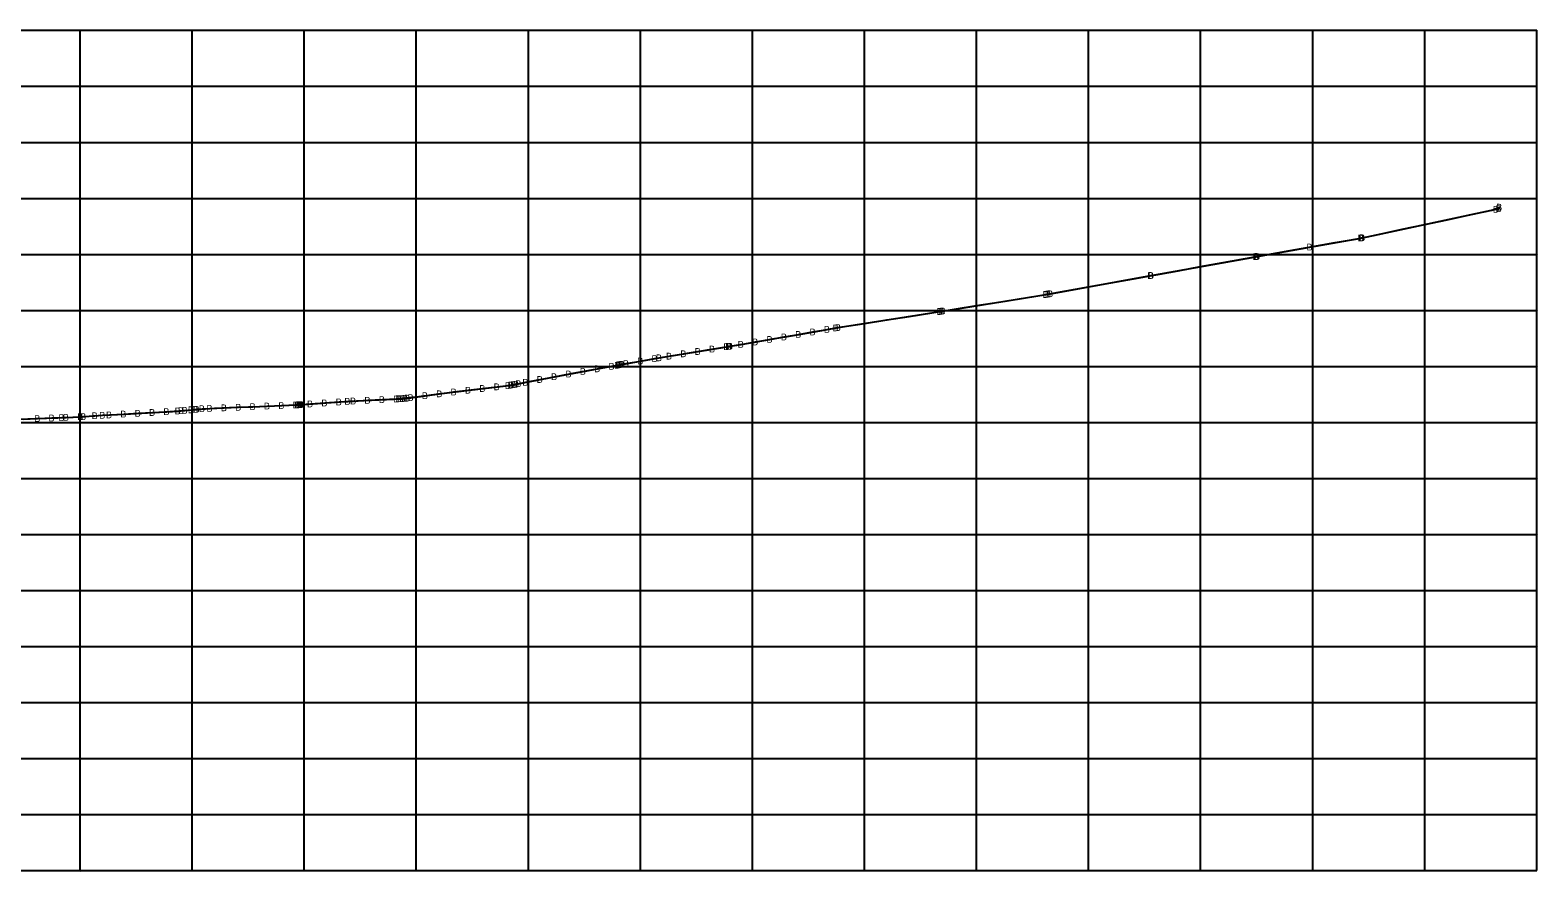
# Model space of a CAD drawing. Extents: x 76292 to 78417, y 50412 to 52585.
# Drawn here: x 77533 to 78206, y 50412 to 50787 of the extents above; entities that cross this region are included whole.
import ezdxf

# ---------------------------------------------------------------- set-up
doc = ezdxf.new("R2010")
doc.units = 0
for name, color, linetype in [('1', 7, 'Continuous'), ('2', 7, 'Continuous'), ('38', 7, 'Continuous'), ('5', 7, 'Continuous'), ('63', 7, 'Continuous')]:
    doc.layers.add(name, color=color, linetype=linetype)

msp = doc.modelspace()

# ---------------------------------------------------------------- linework, layer by layer
at = {"layer": '1'}
for p, q in [((76305.34, 50412.34), (78205.34, 50412.34)), ((77555.34, 50412.34), (77555.34, 50412.34)), ((77605.34, 50412.34), (77605.34, 50412.34)), ((77655.34, 50412.34), (77655.34, 50412.34)), ((77705.34, 50412.34), (77705.34, 50412.34)), ((77755.34, 50412.34), (77755.34, 50412.34)), ((77805.34, 50412.34), (77805.34, 50412.34)), ((77855.34, 50412.34), (77855.34, 50412.34)), ((77905.34, 50412.34), (77905.34, 50412.34)), ((77955.34, 50412.34), (77955.34, 50412.34)), ((78005.34, 50412.34), (78005.34, 50412.34)), ((78055.34, 50412.34), (78055.34, 50412.34)), ((78105.34, 50412.34), (78105.34, 50412.34)), ((78155.34, 50412.34), (78155.34, 50412.34)), ((78205.34, 50412.34), (78205.34, 50412.34))]:
    msp.add_line(p, q, dxfattribs=at)
at = {"layer": '2'}
msp.add_lwpolyline([(77529.92, 50613.86), (77536.33, 50614.1), (77542.74, 50614.35), (77547.18, 50614.53), (77549.14, 50614.61), (77555.55, 50614.9), (77556.82, 50614.96), (77561.96, 50615.32), (77565.36, 50615.56), (77568.37, 50615.72), (77574.77, 50616.07), (77581.18, 50616.43), (77587.59, 50616.79), (77593.99, 50617.16), (77599.01, 50617.45), (77600.4, 50617.57), (77602.11, 50617.72), (77604.87, 50617.97), (77606.81, 50618.16), (77607.41, 50618.22), (77609.78, 50618.47), (77613.22, 50618.61), (77619.62, 50618.87), (77626.03, 50619.13), (77632.44, 50619.39), (77638.84, 50619.64), (77645.25, 50619.89), (77651.66, 50620.14), (77652.43, 50620.17), (77652.93, 50620.21), (77653.35, 50620.26), (77653.73, 50620.3), (77654.09, 50620.33), (77658.06, 50620.62), (77664.47, 50621.06), (77670.88, 50621.49), (77674.74, 50621.74), (77677.29, 50621.89), (77683.69, 50622.23), (77690.1, 50622.55), (77696.51, 50622.85), (77697.44, 50622.89), (77698.34, 50622.91), (77699.33, 50622.96), (77700.38, 50623.06), (77701.41, 50623.19), (77702.91, 50623.4), (77709.32, 50624.28), (77715.73, 50625.12), (77722.13, 50625.94), (77728.54, 50626.74), (77734.95, 50627.5), (77741.36, 50628.24), (77746.33, 50628.8), (77747.54, 50628.96), (77747.76, 50629), (77748.76, 50629.16), (77749.93, 50629.4), (77751.01, 50629.65), (77754.17, 50630.27), (77760.58, 50631.52), (77766.98, 50632.74), (77773.39, 50633.95), (77779.8, 50635.13), (77786.2, 50636.28), (77792.61, 50637.42), (77795.14, 50637.86), (77795.65, 50637.97), (77796.17, 50638.08), (77796.69, 50638.19), (77797.17, 50638.3), (77799.02, 50638.63), (77805.43, 50639.75), (77811.83, 50640.87), (77813.75, 50641.19), (77818.24, 50641.93), (77824.65, 50642.98), (77831.05, 50644.02), (77837.46, 50645.07), (77843.87, 50646.12), (77844.77, 50646.27), (77844.94, 50646.29), (77845.11, 50646.31), (77845.44, 50646.36), (77850.27, 50647.18), (77856.68, 50648.28), (77863.09, 50649.38), (77869.5, 50650.49), (77875.9, 50651.61), (77882.31, 50652.73), (77888.72, 50653.86), (77892.62, 50654.55), (77892.63, 50654.55), (77892.64, 50654.55), (77893.59, 50654.7), (77939.07, 50661.86), (77939.71, 50661.97), (77940.36, 50662.07), (77986.35, 50669.44), (77987.34, 50669.59), (77988.31, 50669.75), (78033.06, 50677.89), (78033.19, 50677.91), (78033.33, 50677.93), (78080.04, 50686.29), (78080.36, 50686.34), (78080.68, 50686.4), (78104.07, 50690.6), (78126.89, 50694.62), (78127.19, 50694.68), (78127.56, 50694.75), (78187.26, 50707.49), (78188.5, 50707.75)], dxfattribs=at)
at = {"layer": '38'}
msp.add_lwpolyline([(77525.34, 50613.7), (77535.34, 50614.07), (77545.34, 50614.45), (77555.34, 50614.89), (77565.34, 50615.55), (77575.34, 50616.1), (77585.34, 50616.67), (77595.34, 50617.24), (77605.34, 50618.02), (77615.34, 50618.7), (77625.34, 50619.11), (77635.34, 50619.5), (77645.34, 50619.89), (77655.34, 50620.42), (77665.34, 50621.12), (77675.34, 50621.78), (77685.34, 50622.31), (77695.34, 50622.79), (77705.34, 50623.73), (77715.34, 50625.07), (77725.34, 50626.34), (77735.34, 50627.55), (77745.34, 50628.68), (77755.34, 50630.5), (77765.34, 50632.43), (77775.34, 50634.3), (77785.34, 50636.13), (77795.34, 50637.9), (77805.34, 50639.74), (77815.34, 50641.45), (77825.34, 50643.09), (77835.34, 50644.72), (77845.34, 50646.34), (77855.34, 50648.05), (77865.34, 50649.77), (77875.34, 50651.51), (77885.34, 50653.26), (77895.34, 50654.98), (77905.34, 50656.55), (77915.34, 50658.13), (77925.34, 50659.7), (77935.34, 50661.28), (77945.34, 50662.86), (77955.34, 50664.47), (77965.34, 50666.07), (77975.34, 50667.68), (77985.34, 50669.28), (77995.34, 50671.03), (78005.34, 50672.84), (78015.34, 50674.66), (78025.34, 50676.48), (78035.34, 50678.29), (78045.34, 50680.08), (78055.34, 50681.87), (78065.34, 50683.66), (78075.34, 50685.45), (78085.34, 50687.23), (78095.34, 50689.03), (78105.34, 50690.82), (78115.34, 50692.58), (78125.34, 50694.35), (78135.34, 50696.41), (78145.34, 50698.55), (78155.34, 50700.68), (78165.34, 50702.81), (78175.34, 50704.95), (78185.34, 50707.08), (78188.7, 50708.41)], dxfattribs=at)
msp.add_lwpolyline([(77525.34, 50613.7), (77535.34, 50614.07), (77545.34, 50614.45), (77555.34, 50614.89), (77565.34, 50615.55), (77575.34, 50616.1), (77585.34, 50616.67), (77595.34, 50617.24), (77605.34, 50618.02), (77615.34, 50618.7), (77625.34, 50619.11), (77635.34, 50619.5), (77645.34, 50619.89), (77655.34, 50620.42), (77665.34, 50621.12), (77675.34, 50621.78), (77685.34, 50622.31), (77695.34, 50622.79), (77705.34, 50623.73), (77715.34, 50625.07), (77725.34, 50626.34), (77735.34, 50627.55), (77745.34, 50628.68), (77755.34, 50630.5), (77765.34, 50632.43), (77775.34, 50634.3), (77785.34, 50636.13), (77795.34, 50637.9), (77805.34, 50639.74), (77815.34, 50641.45), (77825.34, 50643.09), (77835.34, 50644.72), (77845.34, 50646.34), (77855.34, 50648.05), (77865.34, 50649.77), (77875.34, 50651.51), (77885.34, 50653.26), (77895.34, 50654.98), (77905.34, 50656.55), (77915.34, 50658.13), (77925.34, 50659.7), (77935.34, 50661.28), (77945.34, 50662.86), (77955.34, 50664.47), (77965.34, 50666.07), (77975.34, 50667.68), (77985.34, 50669.28), (77995.34, 50671.03), (78005.34, 50672.84), (78015.34, 50674.66), (78025.34, 50676.48), (78035.34, 50678.29), (78045.34, 50680.08), (78055.34, 50681.87), (78065.34, 50683.66), (78075.34, 50685.45), (78085.34, 50687.23), (78095.34, 50689.03), (78105.34, 50690.82), (78115.34, 50692.58), (78125.34, 50694.35), (78135.34, 50696.41), (78145.34, 50698.55), (78155.34, 50700.68), (78165.34, 50702.81), (78175.34, 50704.95), (78185.34, 50707.08), (78188.7, 50708.41)], dxfattribs=at)
at = {"layer": '5'}
for p, q in [((78127.56, 50694.75), (78187.26, 50707.49)), ((78187.26, 50707.49), (78188.5, 50707.75)), ((78188.5, 50707.75), (78188.7, 50708.41)), ((78080.68, 50686.4), (78104.07, 50690.6)), ((78104.07, 50690.6), (78126.89, 50694.62)), ((78126.89, 50694.62), (78127.19, 50694.68)), ((78127.19, 50694.68), (78127.56, 50694.75)), ((78033.33, 50677.93), (78080.04, 50686.29)), ((78080.04, 50686.29), (78080.36, 50686.34)), ((78080.36, 50686.34), (78080.68, 50686.4)), ((77988.31, 50669.75), (78033.06, 50677.89)), ((78033.06, 50677.89), (78033.19, 50677.91)), ((78033.19, 50677.91), (78033.33, 50677.93)), ((77940.36, 50662.07), (77986.35, 50669.44)), ((77986.35, 50669.44), (77987.34, 50669.59)), ((77987.34, 50669.59), (77988.31, 50669.75)), ((77893.59, 50654.7), (77939.07, 50661.86)), ((77939.07, 50661.86), (77939.71, 50661.97)), ((77939.71, 50661.97), (77940.36, 50662.07)), ((77850.27, 50647.18), (77856.68, 50648.28)), ((77856.68, 50648.28), (77863.09, 50649.38)), ((77863.09, 50649.38), (77869.5, 50650.49)), ((77869.5, 50650.49), (77875.9, 50651.61)), ((77875.9, 50651.61), (77882.31, 50652.73)), ((77882.31, 50652.73), (77888.72, 50653.86)), ((77888.72, 50653.86), (77892.62, 50654.55)), ((77892.62, 50654.55), (77892.63, 50654.55)), ((77892.63, 50654.55), (77892.64, 50654.55)), ((77892.64, 50654.55), (77893.59, 50654.7)), ((77813.75, 50641.19), (77818.24, 50641.93)), ((77818.24, 50641.93), (77824.65, 50642.98)), ((77824.65, 50642.98), (77831.05, 50644.02)), ((77831.05, 50644.02), (77837.46, 50645.07)), ((77837.46, 50645.07), (77843.87, 50646.12)), ((77843.87, 50646.12), (77844.77, 50646.27)), ((77844.77, 50646.27), (77844.94, 50646.29)), ((77844.94, 50646.29), (77845.11, 50646.31)), ((77845.11, 50646.31), (77845.44, 50646.36)), ((77845.44, 50646.36), (77850.27, 50647.18)), ((77773.39, 50633.95), (77779.8, 50635.13)), ((77779.8, 50635.13), (77786.2, 50636.28)), ((77786.2, 50636.28), (77792.61, 50637.42)), ((77792.61, 50637.42), (77795.14, 50637.86)), ((77795.14, 50637.86), (77795.65, 50637.97)), ((77795.65, 50637.97), (77796.17, 50638.08)), ((77796.17, 50638.08), (77796.69, 50638.19)), ((77796.69, 50638.19), (77797.17, 50638.3)), ((77797.17, 50638.3), (77799.02, 50638.63)), ((77799.02, 50638.63), (77805.43, 50639.75)), ((77805.43, 50639.75), (77811.83, 50640.87)), ((77811.83, 50640.87), (77813.75, 50641.19)), ((77734.95, 50627.5), (77741.36, 50628.24)), ((77741.36, 50628.24), (77746.33, 50628.8)), ((77746.33, 50628.8), (77747.54, 50628.96)), ((77747.54, 50628.96), (77747.76, 50629)), ((77747.76, 50629), (77748.76, 50629.16)), ((77748.76, 50629.16), (77749.93, 50629.4)), ((77749.93, 50629.4), (77751.01, 50629.65)), ((77751.01, 50629.65), (77754.17, 50630.27)), ((77754.17, 50630.27), (77760.58, 50631.52)), ((77760.58, 50631.52), (77766.98, 50632.74)), ((77766.98, 50632.74), (77773.39, 50633.95)), ((77664.47, 50621.06), (77670.88, 50621.49)), ((77670.88, 50621.49), (77674.74, 50621.74)), ((77674.74, 50621.74), (77677.29, 50621.89)), ((77677.29, 50621.89), (77683.69, 50622.23)), ((77683.69, 50622.23), (77690.1, 50622.55)), ((77690.1, 50622.55), (77696.51, 50622.85)), ((77696.51, 50622.85), (77697.44, 50622.89)), ((77697.44, 50622.89), (77698.34, 50622.91)), ((77698.34, 50622.91), (77699.33, 50622.96)), ((77699.33, 50622.96), (77700.38, 50623.06)), ((77700.38, 50623.06), (77701.41, 50623.19)), ((77701.41, 50623.19), (77702.91, 50623.4)), ((77702.91, 50623.4), (77709.32, 50624.28)), ((77709.32, 50624.28), (77715.73, 50625.12)), ((77715.73, 50625.12), (77722.13, 50625.94)), ((77722.13, 50625.94), (77728.54, 50626.74)), ((77728.54, 50626.74), (77734.95, 50627.5)), ((77547.18, 50614.53), (77549.14, 50614.61)), ((77549.14, 50614.61), (77555.55, 50614.9)), ((77555.55, 50614.9), (77556.82, 50614.96)), ((77556.82, 50614.96), (77561.96, 50615.32)), ((77561.96, 50615.32), (77565.36, 50615.56)), ((77565.36, 50615.56), (77568.37, 50615.72)), ((77568.37, 50615.72), (77574.77, 50616.07)), ((77574.77, 50616.07), (77581.18, 50616.43)), ((77581.18, 50616.43), (77587.59, 50616.79)), ((77587.59, 50616.79), (77593.99, 50617.16)), ((77593.99, 50617.16), (77599.01, 50617.45)), ((77599.01, 50617.45), (77600.4, 50617.57)), ((77600.4, 50617.57), (77602.11, 50617.72)), ((77602.11, 50617.72), (77604.87, 50617.97)), ((77604.87, 50617.97), (77606.81, 50618.16)), ((77606.81, 50618.16), (77607.41, 50618.22)), ((77607.41, 50618.22), (77609.78, 50618.47)), ((77609.78, 50618.47), (77613.22, 50618.61)), ((77613.22, 50618.61), (77619.62, 50618.87)), ((77619.62, 50618.87), (77626.03, 50619.13)), ((77626.03, 50619.13), (77632.44, 50619.39)), ((77632.44, 50619.39), (77638.84, 50619.64)), ((77638.84, 50619.64), (77645.25, 50619.89)), ((77645.25, 50619.89), (77651.66, 50620.14)), ((77651.66, 50620.14), (77652.43, 50620.17)), ((77652.43, 50620.17), (77652.93, 50620.21)), ((77652.93, 50620.21), (77653.35, 50620.26)), ((77653.35, 50620.26), (77653.73, 50620.3)), ((77653.73, 50620.3), (77654.09, 50620.33)), ((77654.09, 50620.33), (77658.06, 50620.62)), ((77658.06, 50620.62), (77664.47, 50621.06)), ((77529.92, 50613.86), (77536.33, 50614.1)), ((77536.33, 50614.1), (77542.74, 50614.35)), ((77542.74, 50614.35), (77547.18, 50614.53))]:
    msp.add_line(p, q, dxfattribs=at)
at = {"layer": '63'}
for p, q in [((76305.34, 50787.34), (78205.34, 50787.34)), ((76305.34, 50787.34), (78205.34, 50787.34)), ((77555.34, 50412.34), (77555.34, 50787.34)), ((77605.34, 50412.34), (77605.34, 50787.34)), ((77655.34, 50412.34), (77655.34, 50787.34)), ((77705.34, 50412.34), (77705.34, 50787.34)), ((77755.34, 50412.34), (77755.34, 50787.34)), ((77805.34, 50412.34), (77805.34, 50787.34)), ((77855.34, 50412.34), (77855.34, 50787.34)), ((77905.34, 50412.34), (77905.34, 50787.34)), ((77955.34, 50412.34), (77955.34, 50787.34)), ((78005.34, 50412.34), (78005.34, 50787.34)), ((78055.34, 50412.34), (78055.34, 50787.34)), ((78105.34, 50412.34), (78105.34, 50787.34)), ((78155.34, 50412.34), (78155.34, 50787.34)), ((78205.34, 50412.34), (78205.34, 50787.34)), ((78205.34, 50787.34), (78205.34, 50787.34)), ((78205.34, 50787.34), (78205.34, 50787.34)), ((76305.34, 50762.34), (78205.34, 50762.34)), ((78205.34, 50762.34), (78205.34, 50762.34)), ((76305.34, 50737.34), (78205.34, 50737.34)), ((78205.34, 50737.34), (78205.34, 50737.34)), ((76305.34, 50712.34), (78205.34, 50712.34)), ((78205.34, 50712.34), (78205.34, 50712.34)), ((76305.34, 50687.34), (78205.34, 50687.34)), ((78205.34, 50687.34), (78205.34, 50687.34)), ((76305.34, 50662.34), (78205.34, 50662.34)), ((78205.34, 50662.34), (78205.34, 50662.34)), ((76305.34, 50637.34), (78205.34, 50637.34)), ((78205.34, 50637.34), (78205.34, 50637.34)), ((76305.34, 50612.34), (78205.34, 50612.34)), ((78205.34, 50612.34), (78205.34, 50612.34)), ((76305.34, 50587.34), (78205.34, 50587.34)), ((78205.34, 50587.34), (78205.34, 50587.34)), ((76305.34, 50562.34), (78205.34, 50562.34)), ((78205.34, 50562.34), (78205.34, 50562.34)), ((76305.34, 50537.34), (78205.34, 50537.34)), ((78205.34, 50537.34), (78205.34, 50537.34)), ((76305.34, 50512.34), (78205.34, 50512.34)), ((78205.34, 50512.34), (78205.34, 50512.34)), ((76305.34, 50487.34), (78205.34, 50487.34)), ((78205.34, 50487.34), (78205.34, 50487.34)), ((76305.34, 50462.34), (78205.34, 50462.34)), ((78205.34, 50462.34), (78205.34, 50462.34)), ((76305.34, 50437.34), (78205.34, 50437.34)), ((78205.34, 50437.34), (78205.34, 50437.34)), ((78205.34, 50412.34), (78205.34, 50412.34))]:
    msp.add_line(p, q, dxfattribs=at)

# ---------------------------------------------------------------- texts
at = {"layer": '1'}
for s, p in [('+50', (77555.4, 50411.81)), ('93', (77605.4, 50411.94)), ('+50', (77655.4, 50411.81)), ('94', (77705.4, 50411.94)), ('+50', (77755.4, 50411.81)), ('95', (77805.4, 50411.94)), ('+50', (77855.4, 50411.81)), ('96', (77905.4, 50411.93)), ('+50', (77955.4, 50411.81)), ('97', (78005.4, 50411.94)), ('+50', (78055.4, 50411.81)), ('98', (78105.4, 50411.94)), ('+50', (78155.4, 50411.81)), ('99', (78205.4, 50411.94))]:
    msp.add_text(s, height=0.12, rotation=90, dxfattribs=at).set_placement(p)
at = {"layer": '5'}
for p in [(78185.76, 50705.99), (78187, 50706.25), (78187.2, 50706.91), (78125.39, 50693.12), (78125.69, 50693.18), (78126.06, 50693.25), (78102.57, 50689.1), (78078.54, 50684.79), (78078.86, 50684.84), (78079.18, 50684.9), (78031.56, 50676.39), (78031.69, 50676.41), (78031.83, 50676.43), (77984.85, 50667.94), (77985.84, 50668.09), (77986.81, 50668.25), (77937.57, 50660.36), (77938.21, 50660.47), (77938.86, 50660.57), (77887.22, 50652.36), (77891.12, 50653.05), (77891.13, 50653.05), (77891.14, 50653.05), (77892.09, 50653.2), (77848.77, 50645.68), (77855.18, 50646.78), (77861.59, 50647.88), (77868, 50648.99), (77874.4, 50650.11), (77880.81, 50651.23), (77810.33, 50639.37), (77812.25, 50639.69), (77816.74, 50640.43), (77823.15, 50641.48), (77829.55, 50642.52), (77835.96, 50643.57), (77842.37, 50644.62), (77843.27, 50644.77), (77843.44, 50644.79), (77843.61, 50644.81), (77843.94, 50644.86), (77771.89, 50632.45), (77778.3, 50633.63), (77784.7, 50634.78), (77791.11, 50635.92), (77793.64, 50636.36), (77794.15, 50636.47), (77794.67, 50636.58), (77795.19, 50636.69), (77795.67, 50636.8), (77797.52, 50637.13), (77803.93, 50638.25), (77727.04, 50625.24), (77733.45, 50626), (77739.86, 50626.74), (77744.83, 50627.3), (77746.04, 50627.46), (77746.26, 50627.5), (77747.26, 50627.66), (77748.43, 50627.9), (77749.51, 50628.15), (77752.67, 50628.77), (77759.08, 50630.02), (77765.48, 50631.24), (77643.75, 50618.39), (77650.16, 50618.64), (77650.93, 50618.67), (77651.43, 50618.71), (77651.85, 50618.76), (77652.23, 50618.8), (77652.59, 50618.83), (77656.56, 50619.12), (77662.97, 50619.56), (77669.38, 50619.99), (77673.24, 50620.24), (77675.79, 50620.39), (77682.19, 50620.73), (77688.6, 50621.05), (77695.01, 50621.35), (77695.94, 50621.39), (77696.84, 50621.41), (77697.83, 50621.46), (77698.88, 50621.56), (77699.91, 50621.69), (77701.41, 50621.9), (77707.82, 50622.78), (77714.23, 50623.62), (77720.63, 50624.44), (77534.83, 50612.6), (77541.24, 50612.85), (77545.68, 50613.03), (77547.64, 50613.11), (77554.05, 50613.4), (77555.32, 50613.46), (77560.46, 50613.82), (77563.86, 50614.06), (77566.87, 50614.22), (77573.27, 50614.57), (77579.68, 50614.93), (77586.09, 50615.29), (77592.49, 50615.66), (77597.51, 50615.95), (77598.9, 50616.07), (77600.61, 50616.22), (77603.37, 50616.47), (77605.31, 50616.66), (77605.91, 50616.72), (77608.28, 50616.97), (77611.72, 50617.11), (77618.12, 50617.37), (77624.53, 50617.63), (77630.94, 50617.89), (77637.34, 50618.14)]:
    msp.add_text('B', height=3, dxfattribs=at).set_placement(p)
at = {"layer": '63'}
for s, p in [('945', (78205.56, 50787.28)), ('945', (78205.56, 50787.28)), ('940', (78205.56, 50762.28)), ('935', (78205.56, 50737.28)), ('930', (78205.56, 50712.28)), ('925', (78205.56, 50687.28)), ('920', (78205.56, 50662.28)), ('915', (78205.56, 50637.28)), ('910', (78205.56, 50612.28)), ('905', (78205.56, 50587.28)), ('900', (78205.56, 50562.28)), ('895', (78205.56, 50537.28)), ('890', (78205.56, 50512.28)), ('885', (78205.56, 50487.28)), ('880', (78205.56, 50462.28)), ('875', (78205.56, 50437.28)), ('870', (78205.56, 50412.28))]:
    msp.add_text(s, height=0.12, dxfattribs=at).set_placement(p)

doc.saveas('drawing.dxf')
